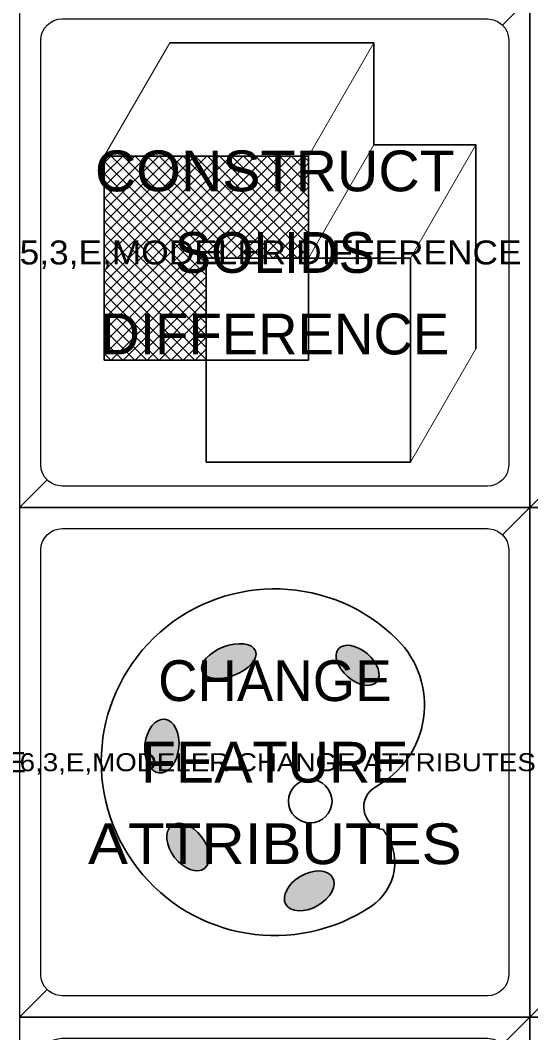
# Model space of a CAD drawing. Extents: x 95909.2 to 95923.3, y 90965 to 90971.2.
# Drawn here: x 95910.988 to 95911.588, y 90967.542 to 90968.734 of the extents above; entities that cross this region are included whole.
import ezdxf
from ezdxf.enums import TextEntityAlignment as Align

# ---------------------------------------------------------------- set-up
doc = ezdxf.new("R2010")
doc.units = 0
doc.header["$LTSCALE"] = 0.019
for name, color, linetype, lineweight in [('1', 7, 'Continuous', 25), ('2', 7, 'Continuous', 25), ('3', 7, 'Continuous', 25), ('4', 7, 'Continuous', 25), ('6', 7, 'Continuous', 13)]:
    doc.layers.add(name, color=color, linetype=linetype, lineweight=lineweight)
doc.layers.add('5', color=7, linetype='Continuous')
doc.layers.add('63', color=7, linetype='Continuous')

msp = doc.modelspace()

# ---------------------------------------------------------------- hatches: boundary and pattern name
at = {"layer": '6'}
h = msp.add_hatch(color=256, dxfattribs=at)
edge = h.paths.add_edge_path()
edge.add_ellipse((95911.23274, 90967.97928), major_axis=(0.03147, 0.01194), ratio=0.529581, start_angle=0, end_angle=360)
h = msp.add_hatch(color=256, dxfattribs=at)
edge = h.paths.add_edge_path()
edge.add_ellipse((95911.38411, 90967.97432), major_axis=(0.02251, -0.01935), ratio=0.5972162, start_angle=0, end_angle=360)
h = msp.add_hatch(color=256, dxfattribs=at)
edge = h.paths.add_edge_path()
edge.add_ellipse((95911.15404, 90967.87925), major_axis=(0.00333, 0.03157), ratio=0.6305197, start_angle=0, end_angle=360)
h = msp.add_hatch(color=256, dxfattribs=at)
edge = h.paths.add_edge_path()
edge.add_ellipse((95911.18484, 90967.76041), major_axis=(-0.01935, 0.02517), ratio=0.6305197, start_angle=0, end_angle=360)
h = msp.add_hatch(color=256, dxfattribs=at)
edge = h.paths.add_edge_path()
edge.add_ellipse((95911.32728, 90967.70881), major_axis=(-0.02749, -0.01588), ratio=0.6305197, start_angle=0, end_angle=360)

# ---------------------------------------------------------------- linework, layer by layer
at = {"layer": '1'}
for points in [[(95910.9868, 90968.1603), (95911.5868, 90968.1603), (95911.5868, 90968.7603), (95910.9868, 90968.7603)], [(95911.5868, 90968.1603), (95912.1868, 90968.1603), (95912.1868, 90968.7603), (95911.5868, 90968.7603)], [(95910.9868, 90967.5603), (95911.5868, 90967.5603), (95911.5868, 90968.1603), (95910.9868, 90968.1603)], [(95911.5868, 90967.5603), (95912.1868, 90967.5603), (95912.1868, 90968.1603), (95911.5868, 90968.1603)], [(95910.9868, 90966.9603), (95911.5868, 90966.9603), (95911.5868, 90967.5603), (95910.9868, 90967.5603)], [(95911.5868, 90966.9603), (95912.1868, 90966.9603), (95912.1868, 90967.5603), (95911.5868, 90967.5603)]]:
    msp.add_lwpolyline(points, close=True, dxfattribs=at)
at = {"layer": '2'}
for points in [[(95910.9868, 90968.1603), (95911.5868, 90968.1603), (95911.5868, 90968.7603), (95910.9868, 90968.7603)], [(95911.5868, 90968.1603), (95912.1868, 90968.1603), (95912.1868, 90968.7603), (95911.5868, 90968.7603)], [(95910.9868, 90967.5603), (95911.5868, 90967.5603), (95911.5868, 90968.1603), (95910.9868, 90968.1603)], [(95911.5868, 90967.5603), (95912.1868, 90967.5603), (95912.1868, 90968.1603), (95911.5868, 90968.1603)], [(95910.9868, 90966.9603), (95911.5868, 90966.9603), (95911.5868, 90967.5603), (95910.9868, 90967.5603)], [(95911.5868, 90966.9603), (95912.1868, 90966.9603), (95912.1868, 90967.5603), (95911.5868, 90967.5603)]]:
    msp.add_lwpolyline(points, close=True, dxfattribs=at)
at = {"layer": '3'}
for points in [[(95911.5868, 90968.7603), (95910.9868, 90968.7603), (95910.9868, 90968.1603), (95911.0191, 90968.1926), (95911.016, 90968.1964), (95911.0137, 90968.2007), (95911.0123, 90968.2054), (95911.0118, 90968.2103), (95911.0118, 90968.7103), (95911.0123, 90968.7152), (95911.0137, 90968.7199), (95911.016, 90968.7242), (95911.0191, 90968.728), (95911.0191, 90968.728), (95911.0229, 90968.7311), (95911.0272, 90968.7334), (95911.0319, 90968.7348), (95911.0368, 90968.7353), (95911.5368, 90968.7353), (95911.5441, 90968.7342), (95911.5486, 90968.7323), (95911.5527, 90968.7296), (95911.5545, 90968.728)], [(95912.1868, 90968.7603), (95911.5868, 90968.7603), (95911.5868, 90968.1603), (95911.6191, 90968.1926), (95911.616, 90968.1964), (95911.6137, 90968.2007), (95911.6123, 90968.2054), (95911.6118, 90968.2103), (95911.6118, 90968.7103), (95911.6123, 90968.7152), (95911.6137, 90968.7199), (95911.616, 90968.7242), (95911.6191, 90968.728), (95911.6191, 90968.728), (95911.6229, 90968.7311), (95911.6272, 90968.7334), (95911.6319, 90968.7348), (95911.6368, 90968.7353), (95912.1368, 90968.7353), (95912.1441, 90968.7342), (95912.1486, 90968.7323), (95912.1527, 90968.7296), (95912.1545, 90968.728)], [(95911.5868, 90968.1603), (95910.9868, 90968.1603), (95910.9868, 90967.5603), (95911.0191, 90967.5926), (95911.016, 90967.5964), (95911.0137, 90967.6007), (95911.0123, 90967.6054), (95911.0118, 90967.6103), (95911.0118, 90968.1103), (95911.0123, 90968.1152), (95911.0137, 90968.1199), (95911.016, 90968.1242), (95911.0191, 90968.128), (95911.0191, 90968.128), (95911.0229, 90968.1311), (95911.0272, 90968.1334), (95911.0319, 90968.1348), (95911.0368, 90968.1353), (95911.5368, 90968.1353), (95911.5441, 90968.1342), (95911.5486, 90968.1323), (95911.5527, 90968.1296), (95911.5545, 90968.128)], [(95912.1868, 90968.1603), (95911.5868, 90968.1603), (95911.5868, 90967.5603), (95911.6191, 90967.5926), (95911.616, 90967.5964), (95911.6137, 90967.6007), (95911.6123, 90967.6054), (95911.6118, 90967.6103), (95911.6118, 90968.1103), (95911.6123, 90968.1152), (95911.6137, 90968.1199), (95911.616, 90968.1242), (95911.6191, 90968.128), (95911.6191, 90968.128), (95911.6229, 90968.1311), (95911.6272, 90968.1334), (95911.6319, 90968.1348), (95911.6368, 90968.1353), (95912.1368, 90968.1353), (95912.1441, 90968.1342), (95912.1486, 90968.1323), (95912.1527, 90968.1296), (95912.1545, 90968.128)], [(95911.5868, 90967.5603), (95910.9868, 90967.5603), (95910.9868, 90966.9603), (95911.0191, 90966.9926), (95911.016, 90966.9964), (95911.0137, 90967.0007), (95911.0123, 90967.0054), (95911.0118, 90967.0103), (95911.0118, 90967.5103), (95911.0123, 90967.5152), (95911.0137, 90967.5199), (95911.016, 90967.5242), (95911.0191, 90967.528), (95911.0191, 90967.528), (95911.0229, 90967.5311), (95911.0272, 90967.5334), (95911.0319, 90967.5348), (95911.0368, 90967.5353), (95911.5368, 90967.5353), (95911.5441, 90967.5342), (95911.5486, 90967.5323), (95911.5527, 90967.5296), (95911.5545, 90967.528)], [(95912.1868, 90967.5603), (95911.5868, 90967.5603), (95911.5868, 90966.9603), (95911.6191, 90966.9926), (95911.616, 90966.9964), (95911.6137, 90967.0007), (95911.6123, 90967.0054), (95911.6118, 90967.0103), (95911.6118, 90967.5103), (95911.6123, 90967.5152), (95911.6137, 90967.5199), (95911.616, 90967.5242), (95911.6191, 90967.528), (95911.6191, 90967.528), (95911.6229, 90967.5311), (95911.6272, 90967.5334), (95911.6319, 90967.5348), (95911.6368, 90967.5353), (95912.1368, 90967.5353), (95912.1441, 90967.5342), (95912.1486, 90967.5323), (95912.1527, 90967.5296), (95912.1545, 90967.528)]]:
    msp.add_lwpolyline(points, close=True, dxfattribs=at)
at = {"layer": '4'}
for points in [[(95910.9868, 90968.1603), (95911.5868, 90968.1603), (95911.5868, 90968.7603), (95911.5545, 90968.728), (95911.5576, 90968.7242), (95911.5599, 90968.7199), (95911.5613, 90968.7152), (95911.5618, 90968.7103), (95911.5618, 90968.2103), (95911.5613, 90968.2054), (95911.5599, 90968.2007), (95911.5576, 90968.1964), (95911.5545, 90968.1926), (95911.5545, 90968.1926), (95911.5507, 90968.1895), (95911.5464, 90968.1872), (95911.5417, 90968.1858), (95911.5368, 90968.1853), (95911.0368, 90968.1853), (95911.0295, 90968.1864), (95911.025, 90968.1883), (95911.0209, 90968.191), (95911.0191, 90968.1926)], [(95911.5868, 90968.1603), (95912.1868, 90968.1603), (95912.1868, 90968.7603), (95912.1545, 90968.728), (95912.1576, 90968.7242), (95912.1599, 90968.7199), (95912.1613, 90968.7152), (95912.1618, 90968.7103), (95912.1618, 90968.2103), (95912.1613, 90968.2054), (95912.1599, 90968.2007), (95912.1576, 90968.1964), (95912.1545, 90968.1926), (95912.1545, 90968.1926), (95912.1507, 90968.1895), (95912.1464, 90968.1872), (95912.1417, 90968.1858), (95912.1368, 90968.1853), (95911.6368, 90968.1853), (95911.6295, 90968.1864), (95911.625, 90968.1883), (95911.6209, 90968.191), (95911.6191, 90968.1926)], [(95910.9868, 90967.5603), (95911.5868, 90967.5603), (95911.5868, 90968.1603), (95911.5545, 90968.128), (95911.5576, 90968.1242), (95911.5599, 90968.1199), (95911.5613, 90968.1152), (95911.5618, 90968.1103), (95911.5618, 90967.6103), (95911.5613, 90967.6054), (95911.5599, 90967.6007), (95911.5576, 90967.5964), (95911.5545, 90967.5926), (95911.5545, 90967.5926), (95911.5507, 90967.5895), (95911.5464, 90967.5872), (95911.5417, 90967.5858), (95911.5368, 90967.5853), (95911.0368, 90967.5853), (95911.0295, 90967.5864), (95911.025, 90967.5883), (95911.0209, 90967.591), (95911.0191, 90967.5926)], [(95911.5868, 90967.5603), (95912.1868, 90967.5603), (95912.1868, 90968.1603), (95912.1545, 90968.128), (95912.1576, 90968.1242), (95912.1599, 90968.1199), (95912.1613, 90968.1152), (95912.1618, 90968.1103), (95912.1618, 90967.6103), (95912.1613, 90967.6054), (95912.1599, 90967.6007), (95912.1576, 90967.5964), (95912.1545, 90967.5926), (95912.1545, 90967.5926), (95912.1507, 90967.5895), (95912.1464, 90967.5872), (95912.1417, 90967.5858), (95912.1368, 90967.5853), (95911.6368, 90967.5853), (95911.6295, 90967.5864), (95911.625, 90967.5883), (95911.6209, 90967.591), (95911.6191, 90967.5926)], [(95910.9868, 90966.9603), (95911.5868, 90966.9603), (95911.5868, 90967.5603), (95911.5545, 90967.528), (95911.5576, 90967.5242), (95911.5599, 90967.5199), (95911.5613, 90967.5152), (95911.5618, 90967.5103), (95911.5618, 90967.0103), (95911.5613, 90967.0054), (95911.5599, 90967.0007), (95911.5576, 90966.9964), (95911.5545, 90966.9926), (95911.5545, 90966.9926), (95911.5507, 90966.9895), (95911.5464, 90966.9872), (95911.5417, 90966.9858), (95911.5368, 90966.9853), (95911.0368, 90966.9853), (95911.0295, 90966.9864), (95911.025, 90966.9883), (95911.0209, 90966.991), (95911.0191, 90966.9926)]]:
    msp.add_lwpolyline(points, close=True, dxfattribs=at)
at = {"layer": '6'}
for p, q in [((95911.0863, 90968.5736), (95911.1633, 90968.707)), ((95911.3263, 90968.5736), (95911.4033, 90968.707)), ((95911.3263, 90968.4536), (95911.4033, 90968.587)), ((95911.4463, 90968.4536), (95911.5233, 90968.587)), ((95911.0863, 90968.566), (95911.0939, 90968.5736)), ((95911.0863, 90968.5519), (95911.108, 90968.5736)), ((95911.0863, 90968.5378), (95911.1221, 90968.5736)), ((95911.0863, 90968.5236), (95911.1363, 90968.5736)), ((95911.0863, 90968.5095), (95911.1504, 90968.5736)), ((95911.0863, 90968.4953), (95911.1646, 90968.5736)), ((95911.0863, 90968.4812), (95911.1787, 90968.5736)), ((95911.0863, 90968.467), (95911.1929, 90968.5736)), ((95911.0863, 90968.4529), (95911.207, 90968.5736)), ((95911.0863, 90968.4388), (95911.2211, 90968.5736)), ((95911.0863, 90968.4246), (95911.2353, 90968.5736)), ((95911.0863, 90968.4105), (95911.2494, 90968.5736)), ((95911.0863, 90968.3963), (95911.2636, 90968.5736)), ((95911.0863, 90968.3822), (95911.2777, 90968.5736)), ((95911.0863, 90968.3681), (95911.2918, 90968.5736)), ((95911.0863, 90968.3539), (95911.306, 90968.5736)), ((95911.0863, 90968.3398), (95911.3201, 90968.5736)), ((95911.0943, 90968.5736), (95911.2143, 90968.4536)), ((95911.1085, 90968.5736), (95911.2285, 90968.4536)), ((95911.1226, 90968.5736), (95911.2426, 90968.4536)), ((95911.1368, 90968.5736), (95911.2568, 90968.4536)), ((95911.1509, 90968.5736), (95911.2709, 90968.4536)), ((95911.165, 90968.5736), (95911.285, 90968.4536)), ((95911.1792, 90968.5736), (95911.2992, 90968.4536)), ((95911.1933, 90968.5736), (95911.3133, 90968.4536)), ((95911.2075, 90968.5736), (95911.3263, 90968.4548)), ((95911.2216, 90968.5736), (95911.3263, 90968.4689)), ((95911.2358, 90968.5736), (95911.3263, 90968.4831)), ((95911.2499, 90968.5736), (95911.3263, 90968.4972)), ((95911.264, 90968.5736), (95911.3263, 90968.5113)), ((95911.2782, 90968.5736), (95911.3263, 90968.5255)), ((95911.2923, 90968.5736), (95911.3263, 90968.5396)), ((95911.3065, 90968.5736), (95911.3263, 90968.5538)), ((95911.3206, 90968.5736), (95911.3263, 90968.5679)), ((95911.0863, 90968.5675), (95911.2063, 90968.4475)), ((95911.2143, 90968.4536), (95911.3263, 90968.5656)), ((95911.0863, 90968.5534), (95911.2063, 90968.4334)), ((95911.2284, 90968.4536), (95911.3263, 90968.5515)), ((95911.0863, 90968.5392), (95911.2063, 90968.4192)), ((95911.2426, 90968.4536), (95911.3263, 90968.5373)), ((95911.0863, 90968.5251), (95911.2063, 90968.4051)), ((95911.2567, 90968.4536), (95911.3263, 90968.5232)), ((95911.0863, 90968.5109), (95911.2063, 90968.3909)), ((95911.2708, 90968.4536), (95911.3263, 90968.5091)), ((95911.0863, 90968.4968), (95911.2063, 90968.3768)), ((95911.285, 90968.4536), (95911.3263, 90968.4949)), ((95911.0863, 90968.4826), (95911.2063, 90968.3626)), ((95911.2991, 90968.4536), (95911.3263, 90968.4808)), ((95911.0863, 90968.4685), (95911.2063, 90968.3485)), ((95911.3133, 90968.4536), (95911.3263, 90968.4666)), ((95911.0863, 90968.4544), (95911.2063, 90968.3344)), ((95911.0863, 90968.4402), (95911.1929, 90968.3336)), ((95911.0943, 90968.3336), (95911.2063, 90968.4456)), ((95911.1084, 90968.3336), (95911.2063, 90968.4315)), ((95911.0863, 90968.4261), (95911.1788, 90968.3336)), ((95911.1226, 90968.3336), (95911.2063, 90968.4173)), ((95911.0863, 90968.4119), (95911.1646, 90968.3336)), ((95911.0863, 90968.3978), (95911.1505, 90968.3336)), ((95911.1367, 90968.3336), (95911.2063, 90968.4032)), ((95911.0863, 90968.3836), (95911.1363, 90968.3336)), ((95911.1508, 90968.3336), (95911.2063, 90968.3891)), ((95911.0863, 90968.3695), (95911.1222, 90968.3336)), ((95911.165, 90968.3336), (95911.2063, 90968.3749)), ((95911.1791, 90968.3336), (95911.2063, 90968.3608)), ((95911.0863, 90968.3554), (95911.1081, 90968.3336)), ((95911.1933, 90968.3336), (95911.2063, 90968.3466)), ((95911.4463, 90968.2136), (95911.5233, 90968.347)), ((95911.0863, 90968.3412), (95911.0939, 90968.3336))]:
    msp.add_line(p, q, dxfattribs=at)
at = {"layer": '6', "lineweight": 35}
msp.add_line((95911.1633, 90968.707), (95911.4033, 90968.707), dxfattribs=at)
msp.add_lwpolyline([(95911.4033, 90968.707), (95911.4033, 90968.587), (95911.5233, 90968.587), (95911.5233, 90968.347)], dxfattribs=at)
for points in [[(95911.0863, 90968.3336), (95911.3263, 90968.3336), (95911.3263, 90968.5736), (95911.0863, 90968.5736)], [(95911.3263, 90968.5736), (95911.0863, 90968.5736), (95911.0863, 90968.3336), (95911.2063, 90968.3336), (95911.2063, 90968.4536), (95911.3263, 90968.4536)], [(95911.2063, 90968.2136), (95911.4463, 90968.2136), (95911.4463, 90968.4536), (95911.2063, 90968.4536)]]:
    msp.add_lwpolyline(points, close=True, dxfattribs=at)
msp.add_circle((95911.32847, 90967.81433), 0.02558, dxfattribs=at)
for centre, radius, start, end in [((95911.28676, 90967.86029), 0.204, 45.13989, 303.90862), ((95911.35364, 90967.92749), 0.10919, 298.38673, 45.14016), ((95911.41841, 90967.80763), 0.02706, 118.38806, 260.86306), ((95911.36617, 90967.74215), 0.06165, 303.90823, 38.95333)]:
    msp.add_arc(centre, radius, start, end, dxfattribs=at)
for centre, major_axis, ratio in [((95911.23274, 90967.97928), (0.03147, 0.01194), 0.529581), ((95911.38411, 90967.97432), (0.02251, -0.01935), 0.597216), ((95911.15404, 90967.87925), (0.00333, 0.03157), 0.63052), ((95911.18484, 90967.76041), (-0.01935, 0.02517), 0.63052), ((95911.32728, 90967.70881), (-0.02749, -0.01588), 0.63052)]:
    msp.add_ellipse(centre, major_axis=major_axis, ratio=ratio, dxfattribs=at)

# ---------------------------------------------------------------- texts
at = {"layer": '5'}
for s, width, p in [('CONSTRUCT', 1.05, (95911.2868, 90968.5323)), ('FEATURE', 1.05, (95911.2868, 90967.8363)), ('ATTRIBUTES', 1.1, (95911.2868, 90967.7403))]:
    msp.add_text(s, height=0.048, dxfattribs=dict(at, width=width)).set_placement(p, align=Align.CENTER)
for s, p in [('SOLIDS', (95911.2868, 90968.4363)), ('DIFFERENCE', (95911.28685, 90968.3403)), ('CHANGE', (95911.28685, 90967.9323))]:
    msp.add_text(s, height=0.048, dxfattribs=at).set_placement(p, align=Align.CENTER)
at = {"layer": '63'}
for s, height, width, p in [('5,3,E,MODELER DIFFERENCE', 0.0282, 1.1, (95910.9868, 90968.4462)), ('6,2,E,MODELER CHANGE PROFILE', 0.0237, 1.15, (95910.3868, 90967.8485)), ('6,3,E,MODELER CHANGE ATTRIBUTES', 0.0212, 1.15, (95910.9868, 90967.8497))]:
    msp.add_text(s, height=height, dxfattribs=dict(at, width=width)).set_placement(p)

doc.saveas('drawing.dxf')
